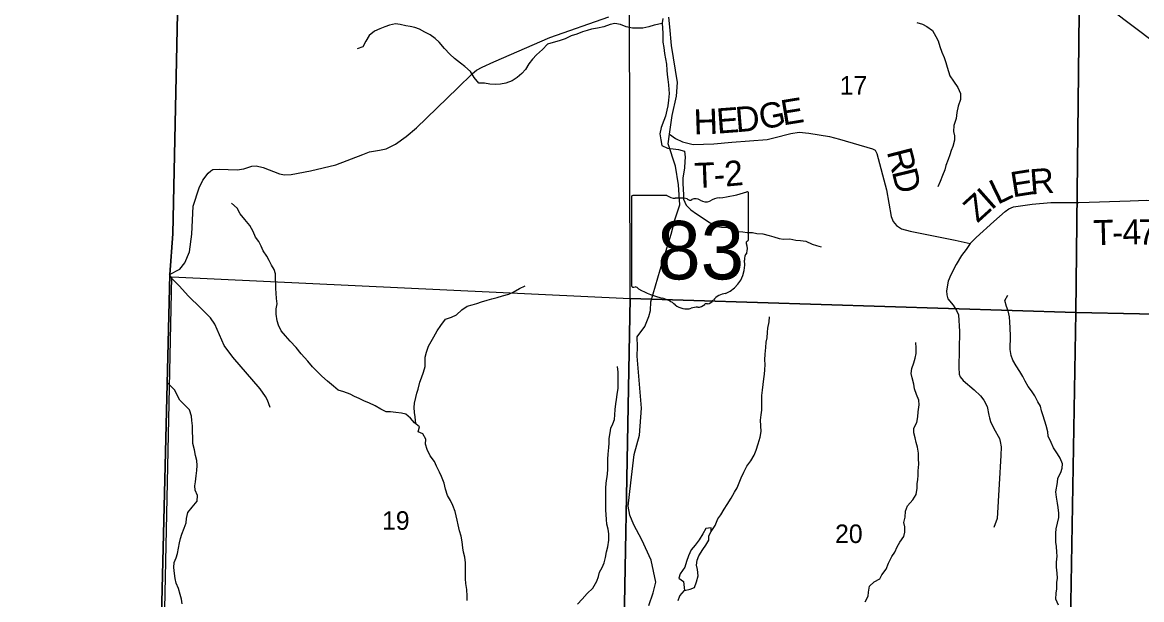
# Model space of a CAD drawing. Extents: x 2043100 to 2470832, y 443715 to 810583.
# Drawn here: x 2192662 to 2205995, y 652233 to 659112 of the extents above; entities that cross this region are included whole.
import ezdxf

# ---------------------------------------------------------------- set-up
doc = ezdxf.new("R2010")
doc.units = 0
for name, color, linetype in [('GM_X_Adjacent_County', 7, 'Continuous'), ('GM_X_County', 7, 'Continuous'), ('GM_X_County_Road', 7, 'Continuous'), ('GM_X_Minor_Lake', 7, 'Continuous'), ('GM_X_Minor_River', 7, 'Continuous'), ('GM_X_Section', 7, 'Continuous'), ('GM_X_Section_Text', 7, 'Continuous'), ('GM_X_State_Location', 7, 'Continuous'), ('GM_X_State_Route', 7, 'Continuous'), ('GM_X_State_Shield', 7, 'Continuous'), ('GM_X_Township', 7, 'Continuous'), ('GM_X_Township_Road', 7, 'Continuous'), ('GM_X_Township_Road_Text', 7, 'Continuous'), ('GM_X_Township_ROW', 7, 'Continuous')]:
    doc.layers.add(name, color=color, linetype=linetype)

msp = doc.modelspace()

# ---------------------------------------------------------------- linework, layer by layer
at = {"layer": 'GM_X_Adjacent_County'}
msp.add_lwpolyline([(2194570, 662033), (2194456, 656593), (2194419, 656109), (2194154, 645194), (2194110, 640430), (2193051, 640461), (2192380, 640460)], dxfattribs=at)
at = {"layer": 'GM_X_County'}
msp.add_lwpolyline([(2209978, 623419), (2210251, 634591), (2210262, 635532), (2210324, 639312), (2210330, 639454), (2210327, 639538), (2204969, 639660), (2200443, 639771), (2194114, 639990), (2194110, 640430), (2194154, 645194), (2194419, 656109), (2194456, 656593), (2194570, 662033)], dxfattribs=at)
at = {"layer": 'GM_X_County_Road'}
msp.add_lwpolyline([(2201432, 661230), (2201433, 661230), (2201841, 661250), (2202197, 661256), (2202605, 661227), (2202894, 661185), (2203102, 661113), (2203522, 660857), (2207731, 657682), (2211539, 655381), (2213116, 654429), (2213391, 654231)], dxfattribs=at)
at = {"layer": 'GM_X_Minor_Lake'}
for points in [[(2200867, 653045), (2200869, 653087), (2200805, 653080), (2200769, 653016), (2200726, 652946), (2200675, 652883), (2200627, 652825), (2200598, 652755), (2200572, 652685), (2200555, 652619), (2200499, 652540), (2200482, 652488), (2200536, 652450), (2200549, 652342)], [(2200549, 652342), (2200615, 652358), (2200667, 652377), (2200692, 652443), (2200712, 652515), (2200703, 652591), (2200693, 652645), (2200700, 652701), (2200722, 652756), (2200767, 652828), (2200805, 652880), (2200838, 652943), (2200840, 652993), (2200867, 653045)]]:
    msp.add_lwpolyline(points, dxfattribs=at)
at = {"layer": 'GM_X_Minor_River'}
for points in [[(2200284, 659098), (2200190, 659077), (2200126, 659058), (2200052, 659042), (2199980, 659041), (2199929, 659043), (2199856, 659060), (2199786, 659087), (2199720, 659097), (2199664, 659086), (2199589, 659060), (2199511, 659043), (2199443, 659031), (2199391, 659016), (2199333, 658998), (2199268, 658973), (2199200, 658950), (2199126, 658916), (2199055, 658893), (2198983, 658873), (2198917, 658852), (2198856, 658790), (2198786, 658723), (2198739, 658672), (2198695, 658616), (2198654, 658552), (2198612, 658501), (2198555, 658453), (2198495, 658414), (2198421, 658386), (2198357, 658375), (2198301, 658371), (2198229, 658376), (2198167, 658387), (2198099, 658389), (2198043, 658453), (2198002, 658526), (2197932, 658586), (2197880, 658627), (2197809, 658683), (2197755, 658734), (2197691, 658800), (2197628, 658876), (2197578, 658921), (2197519, 658965), (2197457, 658996), (2197391, 659032), (2197335, 659049), (2197281, 659061), (2197231, 659070), (2197161, 659088), (2197107, 659095), (2197035, 659079), (2196979, 659060), (2196919, 659036), (2196856, 659005), (2196794, 658955), (2196755, 658886), (2196717, 658820), (2196648, 658795)], [(2200291, 659158), (2200284, 659108), (2200288, 659038), (2200291, 658987), (2200291, 658929), (2200293, 658877), (2200302, 658811), (2200311, 658741), (2200325, 658677), (2200334, 658615), (2200338, 658541), (2200343, 658489), (2200349, 658431), (2200357, 658367), (2200364, 658313), (2200366, 658263), (2200357, 658185), (2200349, 658119), (2200338, 658067), (2200323, 657993), (2200305, 657943), (2200270, 657860), (2200256, 657784), (2200269, 657712), (2200279, 657646), (2200346, 657611), (2200414, 657603), (2200478, 657598), (2200548, 657578), (2200558, 657504), (2200555, 657452), (2200551, 657380), (2200542, 657328), (2200528, 657260), (2200531, 657192), (2200535, 657124), (2200536, 657056), (2200538, 657004), (2200571, 656934), (2200623, 656878), (2200691, 656831), (2200760, 656785), (2200822, 656744), (2200876, 656710), (2200942, 656681), (2200992, 656673), (2201062, 656668), (2201112, 656642), (2201169, 656618), (2201245, 656615), (2201297, 656607), (2201361, 656606), (2201411, 656596), (2201483, 656591), (2201557, 656571), (2201615, 656556), (2201677, 656538), (2201729, 656527), (2201803, 656531), (2201875, 656518), (2201931, 656512), (2201995, 656505), (2202069, 656468), (2202123, 656454), (2202177, 656438)], [(2203317, 659112), (2203383, 659091), (2203435, 659063), (2203505, 659014), (2203544, 658942), (2203570, 658890), (2203591, 658824), (2203615, 658756), (2203642, 658693), (2203664, 658633), (2203679, 658579), (2203695, 658525), (2203711, 658473), (2203754, 658413), (2203806, 658334), (2203839, 658264), (2203838, 658192), (2203810, 658113), (2203793, 658039), (2203785, 657967), (2203758, 657881), (2203755, 657811), (2203765, 657759), (2203767, 657707), (2203746, 657634), (2203726, 657584), (2203709, 657534), (2203689, 657478), (2203664, 657405), (2203650, 657353), (2203621, 657287), (2203594, 657217), (2203568, 657152)], [(2196863, 654541), (2196789, 654579), (2196737, 654598), (2196675, 654628), (2196619, 654653), (2196568, 654679), (2196492, 654708), (2196424, 654730), (2196368, 654775), (2196297, 654835), (2196229, 654894), (2196173, 654952), (2196118, 655006), (2196062, 655075), (2195983, 655163), (2195923, 655238), (2195852, 655312), (2195796, 655375), (2195743, 655437), (2195711, 655503), (2195696, 655555), (2195686, 655635), (2195685, 655699), (2195695, 655759), (2195690, 655823), (2195686, 655883), (2195683, 655941), (2195681, 656001), (2195678, 656055), (2195678, 656115), (2195660, 656167), (2195629, 656219), (2195603, 656272), (2195572, 656326), (2195530, 656390), (2195507, 656444), (2195479, 656500), (2195439, 656551), (2195412, 656619), (2195372, 656689), (2195313, 656764), (2195257, 656832), (2195220, 656896), (2195154, 656957)], [(2197350, 654326), (2197342, 654409), (2197333, 654461), (2197329, 654521), (2197333, 654575), (2197348, 654641), (2197360, 654692), (2197375, 654742), (2197397, 654822), (2197416, 654874), (2197440, 654942), (2197459, 655011), (2197461, 655061), (2197462, 655123), (2197476, 655183), (2197501, 655253), (2197531, 655309), (2197564, 655364), (2197601, 655434), (2197647, 655499), (2197702, 655573), (2197772, 655600), (2197832, 655628), (2197897, 655687), (2197961, 655731), (2198021, 655746), (2198076, 655762), (2198132, 655783), (2198200, 655803), (2198256, 655818), (2198318, 655834), (2198381, 655851), (2198455, 655874), (2198507, 655898), (2198583, 655939), (2198650, 655971)], [(2204989, 652546), (2204981, 652618), (2204980, 652678), (2204988, 652750), (2204985, 652800), (2204979, 652864), (2204974, 652916), (2204972, 652974), (2204971, 653026), (2204975, 653078), (2204993, 653143), (2205008, 653213), (2205008, 653263), (2204999, 653329), (2204993, 653383), (2204980, 653455), (2204972, 653517), (2204993, 653627), (2204996, 653679), (2205032, 653749), (2205047, 653800), (2205053, 653850), (2205024, 653917), (2204994, 653969), (2204947, 654041), (2204917, 654105), (2204882, 654180), (2204876, 654232), (2204857, 654306), (2204821, 654422), (2204802, 654482), (2204790, 654538), (2204759, 654590), (2204721, 654662), (2204682, 654719), (2204644, 654771), (2204609, 654835), (2204579, 654893), (2204543, 654950), (2204502, 655018), (2204460, 655088), (2204441, 655142), (2204427, 655212), (2204428, 655268), (2204434, 655320), (2204433, 655374), (2204429, 655470), (2204426, 655538), (2204422, 655602), (2204405, 655674), (2204387, 655726), (2204366, 655796), (2204402, 655860)], [(2200474, 652223), (2200494, 652277), (2200549, 652342), (2200615, 652358), (2200667, 652377), (2200692, 652443), (2200712, 652515), (2200703, 652591), (2200693, 652645), (2200700, 652701), (2200722, 652756), (2200767, 652828), (2200805, 652880), (2200838, 652943), (2200840, 652993), (2200867, 653045), (2200915, 653117), (2200948, 653194), (2200982, 653244), (2201023, 653312), (2201057, 653365), (2201106, 653443), (2201145, 653512), (2201177, 653564), (2201200, 653624), (2201226, 653682), (2201255, 653751), (2201293, 653823), (2201338, 653887), (2201380, 653956), (2201403, 654012), (2201428, 654090), (2201450, 654169), (2201463, 654237), (2201459, 654303), (2201454, 654371), (2201464, 654435), (2201469, 654489), (2201471, 654547), (2201470, 654665), (2201479, 654727), (2201487, 654797), (2201496, 654865), (2201502, 654918), (2201505, 654970), (2201509, 655036), (2201508, 655090), (2201510, 655156), (2201517, 655238), (2201521, 655302), (2201534, 655354), (2201540, 655418), (2201541, 655468), (2201559, 655543), (2201560, 655603)], [(2202700, 652205), (2202736, 652272), (2202741, 652322), (2202755, 652392), (2202808, 652446), (2202878, 652479), (2202901, 652529), (2202951, 652596), (2202980, 652666), (2203020, 652748), (2203055, 652799), (2203081, 652863), (2203114, 652919), (2203162, 652986), (2203173, 653036), (2203173, 653098), (2203162, 653150), (2203178, 653216), (2203183, 653286), (2203205, 653352), (2203270, 653421), (2203311, 653487), (2203321, 653559), (2203322, 653611), (2203328, 653663), (2203332, 653713), (2203333, 653768), (2203339, 653846), (2203338, 653914), (2203336, 653978), (2203325, 654050), (2203311, 654104), (2203298, 654160), (2203280, 654221), (2203283, 654274), (2203319, 654342), (2203328, 654410), (2203332, 654472), (2203343, 654552), (2203342, 654610), (2203314, 654678), (2203289, 654746), (2203283, 654800), (2203262, 654874), (2203248, 654926), (2203258, 654986), (2203281, 655054), (2203299, 655110), (2203308, 655164), (2203308, 655235), (2203305, 655297)], [(2199276, 652177), (2199331, 652236), (2199391, 652304), (2199456, 652369), (2199505, 652453), (2199523, 652510), (2199536, 652560), (2199568, 652616), (2199591, 652672), (2199609, 652734), (2199622, 652803), (2199638, 652863), (2199647, 652941), (2199649, 653017), (2199642, 653073), (2199626, 653131), (2199619, 653187), (2199615, 653245), (2199612, 653299), (2199614, 653367), (2199611, 653439), (2199611, 653501), (2199612, 653559), (2199618, 653619), (2199633, 653727), (2199637, 653787), (2199638, 653848), (2199638, 653908), (2199641, 653966), (2199647, 654044), (2199650, 654098), (2199650, 654152), (2199663, 654222), (2199673, 654276), (2199694, 654326), (2199714, 654379), (2199721, 654433), (2199725, 654499), (2199732, 654565), (2199740, 654619), (2199747, 654677), (2199761, 654753), (2199759, 654943), (2199751, 655009)], [(2194687, 654305), (2194681, 654367), (2194678, 654419), (2194652, 654493), (2194597, 654551), (2194537, 654610), (2194502, 654678), (2194478, 654730), (2194422, 654785), (2194389, 654817)], [(2197961, 652223), (2197960, 652273), (2197958, 652353), (2197945, 652425), (2197939, 652479), (2197940, 652545), (2197942, 652609), (2197939, 652669), (2197931, 652737), (2197918, 652797), (2197908, 652851), (2197901, 652921), (2197889, 652987), (2197870, 653054), (2197854, 653124), (2197843, 653180), (2197829, 653232), (2197816, 653284), (2197790, 653356), (2197761, 653412), (2197725, 653472), (2197702, 653547), (2197686, 653621), (2197655, 653699), (2197631, 653753), (2197594, 653823), (2197572, 653877), (2197521, 653948), (2197483, 654020), (2197464, 654086), (2197466, 654146), (2197433, 654208), (2197375, 654231), (2197393, 654293), (2197332, 654339), (2197286, 654393), (2197230, 654442), (2197180, 654454), (2197112, 654463), (2197048, 654469), (2196994, 654470), (2196930, 654502), (2196863, 654541)], [(2194566, 652183), (2194556, 652237), (2194543, 652293), (2194521, 652364), (2194494, 652430), (2194480, 652484), (2194473, 652544), (2194467, 652616), (2194470, 652674), (2194492, 652730), (2194510, 652783), (2194523, 652845), (2194534, 652909), (2194544, 652959), (2194562, 653011), (2194591, 653084), (2194611, 653148), (2194618, 653198), (2194632, 653270), (2194683, 653336), (2194742, 653405), (2194746, 653475), (2194721, 653535), (2194717, 653587), (2194723, 653637), (2194732, 653707), (2194739, 653771), (2194743, 653831), (2194738, 653891), (2194726, 653949), (2194712, 654019), (2194693, 654093), (2194691, 654143), (2194690, 654253), (2194687, 654305)], [(2205006, 652166), (2204974, 652238), (2204975, 652310), (2204983, 652362), (2204986, 652436), (2204992, 652488), (2204989, 652546)]]:
    msp.add_lwpolyline(points, dxfattribs=at)
at = {"layer": 'GM_X_Section'}
for points in [[(2205269, 661015), (2205213, 655656), (2199901, 655821), (2199891, 661216)], [(2210610, 660875), (2210522, 655544), (2205213, 655656), (2205269, 661015)], [(2194442, 656079), (2199901, 655821), (2199801, 650468), (2194324, 650570), (2194339, 651181)], [(2199901, 655821), (2205213, 655656), (2205120, 650357), (2199801, 650468)], [(2205213, 655656), (2210522, 655544), (2210438, 650213), (2205120, 650357)]]:
    msp.add_lwpolyline(points, close=True, dxfattribs=at)
at = {"layer": 'GM_X_State_Route'}
msp.add_lwpolyline([(2200125, 652164), (2200176, 652315), (2200208, 652442), (2200151, 652702), (2200042, 652946), (2199944, 653124), (2199900, 653240), (2199877, 653345), (2199912, 653625), (2199951, 653960), (2200013, 654192), (2200036, 654513), (2199986, 655134), (2199988, 655244), (2199987, 655366), (2200075, 655486), (2200124, 655608), (2200143, 655678), (2200147, 655782), (2200261, 656164), (2200391, 656589), (2200438, 656771), (2200494, 656936), (2200479, 657175), (2200443, 657400), (2200355, 657664), (2200371, 657778), (2200403, 658001), (2200454, 658231), (2200465, 658395), (2200396, 658835), (2200376, 659057), (2200363, 659175)], dxfattribs=at)
at = {"layer": 'GM_X_State_Shield'}
for p, q in [((2201311, 656523), (2201311, 657076)), ((2199919, 657032), (2199919, 655975)), ((2200340, 657050), (2199933, 657050)), ((2201311, 656523), (2201311, 656523))]:
    msp.add_line(p, q, dxfattribs=at)
for centre, radius, start, end in [((2200815, 658490), 1476, 275.8445, 288.9065), ((2201296, 657078), 15.5, 351.8621, 97.738), ((2199935, 657034), 16.1, 98.1301, 188.1301), ((2200437, 657172), 156, 231.6195, 271.1119), ((2200489, 656456), 562, 80.4867, 94.9883), ((2200617, 657039), 45.1, 219.7921, 297.1024), ((2200683, 656917), 93.8, 54.4667, 119.1411), ((2200804, 657085), 113, 233.8562, 294.8282), ((2201004, 656727), 297, 97.3462, 120.7689), ((2201295, 656521), 16.6, 289.6038, 7.7341), ((2201308, 656483), 24, 107.944, 210.337), ((2201155, 656413), 144, 340.033, 23.6496), ((2200898, 656222), 369, 292.3089, 8.9858), ((2201367, 656292), 105, 136.8065, 186.9296), ((2199935, 655973), 16.3, 171.9584, 258.3066), ((2199937, 656081), 124, 267.339, 280.6039), ((2199963, 655914), 44.8, 29.7484, 93.2717), ((2200528, 656863), 1066, 240.4129, 257.1985), ((2201054, 655678), 202, 94.4031, 142.5768), ((2200210, 655500), 334, 47.1842, 75.836), ((2200571, 655909), 212, 230.7004, 286.2918), ((2200709, 655830), 113, 268.777, 315.5493), ((2200811, 655727), 31.8, 65.7517, 132.6484), ((2200797, 655872), 119, 282.8732, 323.2771), ((2200693, 655543), 174, 85.6951, 111.2099)]:
    msp.add_arc(centre, radius, start, end, dxfattribs=at)
at = {"layer": 'GM_X_Township'}
msp.add_lwpolyline([(2221192, 660299), (2221175, 657999), (2221149, 653364), (2221048, 648018), (2221044, 645934), (2220986, 642635), (2220927, 639237), (2219619, 639266), (2216075, 639353), (2210327, 639538), (2204969, 639660), (2200443, 639771), (2194114, 639990), (2194110, 640430), (2194154, 645194), (2194419, 656109), (2194456, 656593), (2194570, 662033)], dxfattribs=at)
at = {"layer": 'GM_X_Township_Road'}
for points in [[(2200371, 657778), (2200444, 657728), (2200524, 657688), (2200654, 657658), (2200899, 657664), (2201115, 657683), (2201535, 657717), (2201613, 657737), (2201815, 657789), (2201915, 657805), (2202031, 657791), (2202275, 657752), (2202395, 657720), (2202790, 657606), (2202820, 657588), (2202842, 657550), (2202954, 657115), (2203013, 656797), (2203035, 656737), (2203073, 656689), (2203133, 656651), (2203239, 656623), (2203774, 656517), (2203954, 656477), (2203906, 656405), (2203850, 656333), (2203786, 656227), (2203721, 656105), (2203691, 656027), (2203669, 655914), (2203675, 655864), (2203687, 655818), (2203751, 655740), (2203791, 655678), (2203815, 655626), (2203825, 655428), (2203819, 654997), (2203823, 654921), (2203835, 654887), (2203869, 654843), (2204001, 654733), (2204077, 654661), (2204115, 654609), (2204153, 654535), (2204175, 654429), (2204184, 654398)], [(2203954, 656477), (2204024, 656547), (2204236, 656740), (2204368, 656858), (2204414, 656890), (2204470, 656914), (2204692, 656947), (2204913, 656965), (2205247, 656967), (2205859, 656984), (2206057, 656992), (2206213, 656974), (2206354, 656944), (2206532, 656892), (2206692, 656803)], [(2204184, 654398), (2204184, 654397), (2204195, 654357), (2204235, 654271), (2204301, 654151), (2204311, 654117), (2204323, 654053), (2204319, 653951), (2204299, 653610), (2204274, 653198), (2204233, 653092)]]:
    msp.add_lwpolyline(points, dxfattribs=at)
at = {"layer": 'GM_X_Township_ROW'}
for points in [[(2194414, 656108), (2194538, 656169), (2194596, 656248), (2194652, 656377), (2194682, 656586), (2194698, 656922), (2194767, 657140), (2194813, 657230), (2194875, 657313), (2194905, 657343), (2194931, 657357), (2195005, 657363), (2195221, 657355), (2195301, 657365), (2195397, 657399), (2195447, 657401), (2195529, 657381), (2195725, 657305), (2195785, 657295), (2195865, 657297), (2196094, 657342), (2196394, 657414), (2196716, 657539), (2196798, 657569), (2196918, 657589), (2196994, 657603), (2197106, 657661), (2197232, 657753), (2197355, 657854), (2197845, 658327), (2198025, 658503), (2198071, 658541), (2198139, 658579), (2198277, 658641), (2198944, 658930), (2199649, 659179)], [(2195615, 654523), (2195582, 654608), (2195558, 654654), (2195496, 654744), (2195168, 655122), (2195064, 655262), (2194956, 655514), (2194904, 655591), (2194785, 655708), (2194639, 655848), (2194529, 655970), (2194437, 656064), (2194414, 656108)]]:
    msp.add_lwpolyline(points, dxfattribs=at)

# ---------------------------------------------------------------- texts
at = {"layer": 'GM_X_Section_Text'}
for s, p in [('17', (2202398, 658251)), ('19', (2196946, 653065)), ('20', (2202343, 652907))]:
    msp.add_text(s, height=220.8, rotation=0, dxfattribs=at).set_placement(p)
at = {"layer": 'GM_X_State_Location'}
for s in ['s', 'r']:
    msp.add_text(s, height=0.0000833, dxfattribs=at).set_placement((2200600, 656433))
msp.add_text('83', height=0.0000833, rotation=0, dxfattribs=at).set_placement((2200347, 656360))
at = {"layer": 'GM_X_State_Shield'}
msp.add_text('83', height=696.1, dxfattribs=at).set_placement((2200224, 656049))
at = {"layer": 'GM_X_Township_Road_Text'}
for s, rotation, p in [('G', 11.6742, (2201469, 657830)), ('E', 9.2714, (2201724, 657883)), ('H', 1.9419, (2200663, 657775)), ('E', 4.3418, (2200941, 657785)), ('D', 4.8398, (2201167, 657802)), ('R', 284.4414, (2202957, 657571)), ('2', 5.39, (2201039, 657154)), ('T', 2.242, (2200674, 657136)), ('D', 283.6917, (2203018, 657333)), ('E', 8.972, (2204459, 657026)), ('R', 4.3795, (2204674, 657060)), ('-', 3.7099, (2200907, 657146)), ('L', 25.8252, (2204279, 656935)), ('Z', 42.3019, (2204040, 656715)), ('I', 41.6258, (2204205, 656865)), ('T', 1.5387, (2205421, 656454)), ('4', 0.968, (2205768, 656463)), ('7', 358.9487, (2205950, 656466)), ('-', 1.4208, (2205646, 656460))]:
    msp.add_text(s, height=300, rotation=rotation, dxfattribs=at).set_placement(p)

doc.saveas('drawing.dxf')
